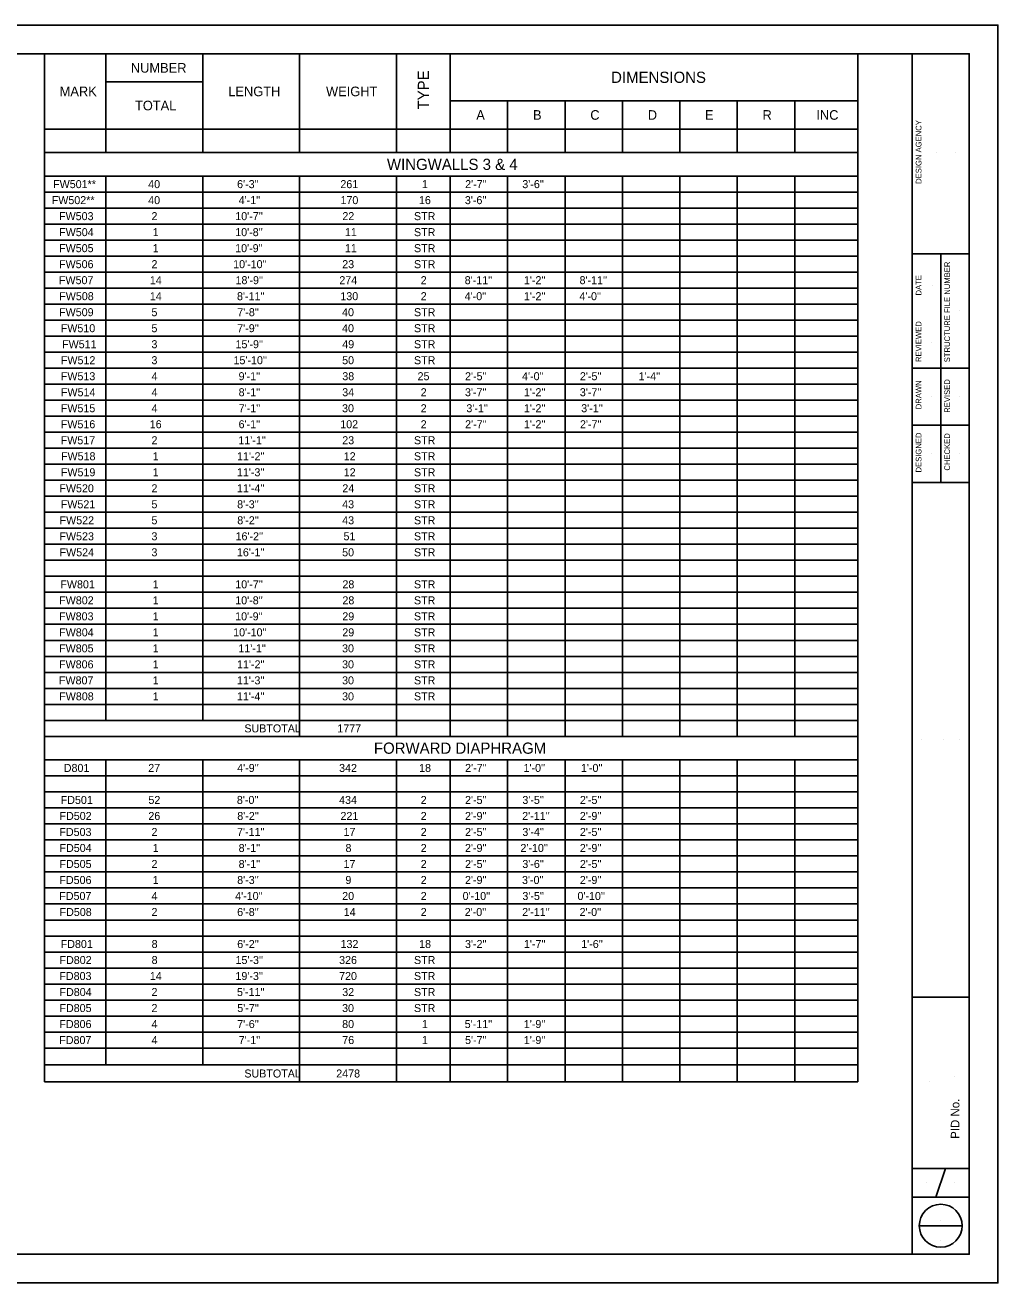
# Model space of a CAD drawing. Extents: x 0 to 34, y 0 to 22.
# Drawn here: x 16.98 to 34, y 0 to 22 of the extents above; entities that cross this region are included whole.
import ezdxf

# ---------------------------------------------------------------- set-up
doc = ezdxf.new("R2010")
doc.units = 0
for name, color, linetype in [('SH_Border', 7, 'Continuous'), ('SH_Cut_Line', 7, 'Continuous'), ('SH_Data', 7, 'Continuous'), ('SH_Text', 7, 'Continuous')]:
    doc.layers.add(name, color=color, linetype=linetype)

msp = doc.modelspace()

# ---------------------------------------------------------------- linework, layer by layer
at = {"layer": 'SH_Border'}
for p, q in [((32.5, 0.5), (32.5, 21.5)), ((32.5, 18), (33.5, 18)), ((33, 14), (33, 18)), ((32.5, 16), (33.5, 16)), ((32.5, 15), (33.5, 15)), ((32.5, 14), (33.5, 14)), ((32.5, 5), (33.5, 5)), ((32.5, 2), (33.5, 2)), ((32.917, 1.5), (33.083, 2)), ((32.5, 1.5), (33.5, 1.5))]:
    msp.add_line(p, q, dxfattribs=at)
msp.add_lwpolyline([(2, 21.5), (33.5, 21.5), (33.5, 0.5), (2, 0.5)], close=True, dxfattribs=at)
at = {"layer": 'SH_Cut_Line'}
msp.add_lwpolyline([(0, 22), (34, 22), (34, 0), (0, 0)], close=True, dxfattribs=at)
at = {"layer": 'SH_Data'}
for p, q in [((17.318, 21.5), (31.548, 21.5)), ((17.318, 21.5), (17.318, 19.771)), ((18.388, 21.5), (18.388, 19.771)), ((20.085, 21.5), (20.085, 19.771)), ((21.781, 21.5), (21.781, 19.771)), ((23.478, 21.5), (23.478, 19.771)), ((24.416, 21.5), (24.416, 19.771)), ((31.548, 21.5), (31.548, 19.771)), ((18.388, 21.006), (20.085, 21.006)), ((24.416, 20.676), (31.548, 20.676)), ((25.421, 20.676), (25.421, 19.771)), ((26.426, 20.676), (26.426, 19.771)), ((27.431, 20.676), (27.431, 19.771)), ((28.435, 20.676), (28.435, 19.771)), ((29.44, 20.676), (29.44, 19.771)), ((30.445, 20.676), (30.445, 19.771)), ((17.318, 20.182), (31.548, 20.182)), ((17.318, 19.771), (31.548, 19.771)), ((17.318, 19.771), (31.548, 19.771)), ((17.318, 19.771), (17.318, 3.514)), ((31.548, 19.771), (31.548, 3.514)), ((32.921, 19.773), (32.921, 19.773)), ((33.254, 19.773), (33.254, 19.773)), ((17.318, 19.359), (31.548, 19.359)), ((18.388, 19.359), (18.388, 9.839)), ((20.085, 19.359), (20.085, 9.839)), ((21.781, 19.359), (21.781, 9.559)), ((23.478, 19.359), (23.478, 9.559)), ((24.416, 19.359), (24.416, 9.559)), ((25.421, 19.359), (25.421, 9.559)), ((26.426, 19.359), (26.426, 9.559)), ((27.431, 19.359), (27.431, 9.559)), ((28.435, 19.359), (28.435, 9.559)), ((29.44, 19.359), (29.44, 9.559)), ((30.445, 19.359), (30.445, 9.559)), ((17.318, 19.079), (31.548, 19.079)), ((17.318, 18.799), (31.548, 18.799)), ((17.318, 18.519), (31.548, 18.519)), ((17.318, 18.239), (31.548, 18.239)), ((17.318, 17.959), (31.548, 17.959)), ((17.318, 17.679), (31.548, 17.679)), ((17.318, 17.399), (31.548, 17.399)), ((32.86, 17.449), (32.86, 17.449)), ((17.318, 17.119), (31.548, 17.119)), ((33.333, 17.009), (33.333, 17.009)), ((17.318, 16.839), (31.548, 16.839)), ((17.318, 16.559), (31.548, 16.559)), ((32.833, 16.447), (32.833, 16.447)), ((17.318, 16.279), (31.548, 16.279)), ((17.318, 15.999), (31.548, 15.999)), ((17.318, 15.719), (31.548, 15.719)), ((17.318, 15.439), (31.548, 15.439)), ((32.833, 15.51), (32.833, 15.51)), ((33.333, 15.51), (33.333, 15.51)), ((17.318, 15.159), (31.548, 15.159)), ((17.318, 14.879), (31.548, 14.879)), ((17.318, 14.599), (31.548, 14.599)), ((17.318, 14.319), (31.548, 14.319)), ((32.833, 14.51), (32.833, 14.51)), ((33.333, 14.509), (33.333, 14.509)), ((17.318, 14.039), (31.548, 14.039)), ((17.318, 13.759), (31.548, 13.759)), ((17.318, 13.479), (31.548, 13.479)), ((17.318, 13.199), (31.548, 13.199)), ((17.318, 12.919), (31.548, 12.919)), ((17.318, 12.639), (31.548, 12.639)), ((17.318, 12.359), (31.548, 12.359)), ((17.318, 12.079), (31.548, 12.079)), ((17.318, 11.799), (31.548, 11.799)), ((17.318, 11.519), (31.548, 11.519)), ((17.318, 11.239), (31.548, 11.239)), ((17.318, 10.959), (31.548, 10.959)), ((17.318, 10.679), (31.548, 10.679)), ((17.318, 10.399), (31.548, 10.399)), ((17.318, 10.119), (31.548, 10.119)), ((17.318, 9.839), (21.781, 9.839)), ((21.781, 9.839), (31.548, 9.839)), ((17.318, 9.559), (31.548, 9.559)), ((32.667, 9.5), (32.667, 9.5)), ((33.042, 9.5), (33.042, 9.5)), ((33.333, 9.5), (33.333, 9.5)), ((17.318, 9.147), (31.548, 9.147)), ((18.388, 9.147), (18.388, 3.811)), ((20.085, 9.147), (20.085, 3.811)), ((21.781, 9.147), (21.781, 3.514)), ((23.478, 9.147), (23.478, 3.514)), ((24.416, 9.147), (24.416, 3.514)), ((25.421, 9.147), (25.421, 3.514)), ((26.426, 9.147), (26.426, 3.514)), ((27.431, 9.147), (27.431, 3.514)), ((28.435, 9.147), (28.435, 3.514)), ((29.44, 9.147), (29.44, 3.514)), ((30.445, 9.147), (30.445, 3.514)), ((17.318, 8.867), (31.548, 8.867)), ((17.318, 8.587), (31.548, 8.587)), ((17.318, 8.307), (31.548, 8.307)), ((17.318, 8.027), (31.548, 8.027)), ((17.318, 7.747), (31.548, 7.747)), ((17.318, 7.467), (31.548, 7.467)), ((17.318, 7.187), (31.548, 7.187)), ((17.318, 6.907), (31.548, 6.907)), ((17.318, 6.627), (31.548, 6.627)), ((17.318, 6.347), (31.548, 6.347)), ((17.318, 6.067), (31.548, 6.067)), ((17.318, 5.787), (31.548, 5.787)), ((17.318, 5.507), (31.548, 5.507)), ((17.318, 5.227), (31.548, 5.227)), ((17.318, 4.947), (31.548, 4.947)), ((17.318, 4.667), (31.548, 4.667)), ((17.318, 4.387), (31.548, 4.387)), ((17.318, 4.107), (31.548, 4.107)), ((17.318, 3.811), (21.781, 3.811)), ((21.781, 3.811), (31.548, 3.811)), ((32.8, 3.53), (32.8, 3.53)), ((33.25, 3.618), (33.25, 3.618)), ((17.318, 3.514), (31.548, 3.514)), ((32.75, 1.75), (32.75, 1.75)), ((33.25, 1.75), (33.25, 1.75)), ((32.625, 1), (33.375, 1)), ((33, 1.085), (33, 1.085)), ((33, 0.745), (33, 0.745))]:
    msp.add_line(p, q, dxfattribs=at)
msp.add_circle((33, 1), 0.375, dxfattribs=at)

# ---------------------------------------------------------------- texts
for s, height, p in [('DESIGN AGENCY', 0.1, (32.663, 19.224)), ('STRUCTURE FILE NUMBER', 0.1, (33.163, 16.103)), ('DATE', 0.1, (32.663, 17.271)), ('REVIEWED', 0.1, (32.663, 16.108)), ('DRAWN', 0.1, (32.663, 15.281)), ('REVISED', 0.1, (33.163, 15.22)), ('DESIGNED', 0.1, (32.663, 14.175)), ('CHECKED', 0.1, (33.163, 14.208)), ('PID No.', 0.15, (33.327, 2.519))]:
    msp.add_text(s, height=height, rotation=90, dxfattribs=at).set_placement(p)
at = {"layer": 'SH_Text'}
for s, height, p in [('NUMBER', 0.168, (18.828, 21.169)), ('DIMENSIONS', 0.196, (27.232, 20.99)), ('MARK', 0.168, (17.582, 20.757)), ('LENGTH', 0.168, (20.533, 20.757)), ('WEIGHT', 0.168, (22.243, 20.757)), ('TOTAL', 0.168, (18.9, 20.51)), ('A', 0.168, (24.872, 20.345)), ('B', 0.168, (25.865, 20.345)), ('C', 0.168, (26.868, 20.345)), ('D', 0.168, (27.874, 20.345)), ('E', 0.168, (28.876, 20.345)), ('R', 0.168, (29.882, 20.345)), ('INC', 0.168, (30.824, 20.345)), ('WINGWALLS 3 & 4', 0.196, (23.309, 19.467)), ('FW501**', 0.14, (17.467, 19.149)), ('40', 0.14, (19.131, 19.149)), ("6'-3''", 0.14, (20.687, 19.149)), ('261', 0.14, (22.494, 19.149)), ('1', 0.14, (23.921, 19.149)), ("2'-7''", 0.14, (24.677, 19.149)), ("3'-6''", 0.14, (25.678, 19.149)), ('FW502**', 0.14, (17.443, 18.869)), ('40', 0.14, (19.131, 18.869)), ("4'-1''", 0.14, (20.714, 18.869)), ('170', 0.14, (22.496, 18.869)), ('16', 0.14, (23.869, 18.869)), ("3'-6''", 0.14, (24.673, 18.869)), ('FW503', 0.14, (17.571, 18.589)), ('2', 0.14, (19.189, 18.589)), ("10'-7''", 0.14, (20.655, 18.589)), ('22', 0.14, (22.529, 18.589)), ('STR', 0.14, (23.782, 18.589)), ('FW504', 0.14, (17.573, 18.309)), ('1', 0.14, (19.21, 18.309)), ("10'-8''", 0.14, (20.654, 18.309)), ('11', 0.14, (22.573, 18.309)), ('STR', 0.14, (23.782, 18.309)), ('FW505', 0.14, (17.572, 18.029)), ('1', 0.14, (19.21, 18.029)), ("10'-9''", 0.14, (20.653, 18.029)), ('11', 0.14, (22.573, 18.029)), ('STR', 0.14, (23.782, 18.029)), ('FW506', 0.14, (17.571, 17.749)), ('2', 0.14, (19.189, 17.749)), ("10'-10''", 0.14, (20.618, 17.749)), ('23', 0.14, (22.527, 17.749)), ('STR', 0.14, (23.782, 17.749)), ('FW507', 0.14, (17.569, 17.469)), ('14', 0.14, (19.16, 17.469)), ("18'-9''", 0.14, (20.659, 17.469)), ('274', 0.14, (22.476, 17.469)), ('2', 0.14, (23.9, 17.469)), ("8'-11''", 0.14, (24.67, 17.469)), ("1'-2''", 0.14, (25.706, 17.469)), ("8'-11''", 0.14, (26.68, 17.469)), ('FW508', 0.14, (17.574, 17.189)), ('14', 0.14, (19.16, 17.189)), ("8'-11''", 0.14, (20.685, 17.189)), ('130', 0.14, (22.494, 17.189)), ('2', 0.14, (23.9, 17.189)), ("4'-0''", 0.14, (24.669, 17.189)), ("1'-2''", 0.14, (25.706, 17.189)), ("4'-0''", 0.14, (26.678, 17.189)), ('FW509', 0.14, (17.572, 16.909)), ('5', 0.14, (19.188, 16.909)), ("7'-8''", 0.14, (20.69, 16.909)), ('40', 0.14, (22.524, 16.909)), ('STR', 0.14, (23.782, 16.909)), ('FW510', 0.14, (17.601, 16.629)), ('5', 0.14, (19.188, 16.629)), ("7'-9''", 0.14, (20.689, 16.629)), ('40', 0.14, (22.524, 16.629)), ('STR', 0.14, (23.782, 16.629)), ('FW511', 0.14, (17.624, 16.349)), ('3', 0.14, (19.188, 16.349)), ("15'-9''", 0.14, (20.659, 16.349)), ('49', 0.14, (22.527, 16.349)), ('STR', 0.14, (23.782, 16.349)), ('FW512', 0.14, (17.603, 16.069)), ('3', 0.14, (19.188, 16.069)), ("15'-10''", 0.14, (20.624, 16.069)), ('50', 0.14, (22.525, 16.069)), ('STR', 0.14, (23.782, 16.069)), ('FW513', 0.14, (17.602, 15.789)), ('4', 0.14, (19.19, 15.789)), ("9'-1''", 0.14, (20.713, 15.789)), ('38', 0.14, (22.528, 15.789)), ('25', 0.14, (23.845, 15.789)), ("2'-5''", 0.14, (24.676, 15.789)), ("4'-0''", 0.14, (25.674, 15.789)), ("2'-5''", 0.14, (26.686, 15.789)), ("1'-4''", 0.14, (27.714, 15.789)), ('FW514', 0.14, (17.604, 15.509)), ('4', 0.14, (19.19, 15.509)), ("8'-1''", 0.14, (20.714, 15.509)), ('34', 0.14, (22.527, 15.509)), ('2', 0.14, (23.9, 15.509)), ("3'-7''", 0.14, (24.675, 15.509)), ("1'-2''", 0.14, (25.706, 15.509)), ("3'-7''", 0.14, (26.685, 15.509)), ('FW515', 0.14, (17.602, 15.229)), ('4', 0.14, (19.19, 15.229)), ("7'-1''", 0.14, (20.715, 15.229)), ('30', 0.14, (22.524, 15.229)), ('2', 0.14, (23.9, 15.229)), ("3'-1''", 0.14, (24.699, 15.229)), ("1'-2''", 0.14, (25.706, 15.229)), ("3'-1''", 0.14, (26.709, 15.229)), ('FW516', 0.14, (17.602, 14.949)), ('16', 0.14, (19.158, 14.949)), ("6'-1''", 0.14, (20.713, 14.949)), ('102', 0.14, (22.492, 14.949)), ('2', 0.14, (23.9, 14.949)), ("2'-7''", 0.14, (24.677, 14.949)), ("1'-2''", 0.14, (25.706, 14.949)), ("2'-7''", 0.14, (26.687, 14.949)), ('FW517', 0.14, (17.6, 14.669)), ('2', 0.14, (19.189, 14.669)), ("11'-1''", 0.14, (20.709, 14.669)), ('23', 0.14, (22.527, 14.669)), ('STR', 0.14, (23.782, 14.669)), ('FW518', 0.14, (17.605, 14.389)), ('1', 0.14, (19.21, 14.389)), ("11'-2''", 0.14, (20.686, 14.389)), ('12', 0.14, (22.553, 14.389)), ('STR', 0.14, (23.782, 14.389)), ('FW519', 0.14, (17.603, 14.109)), ('1', 0.14, (19.21, 14.109)), ("11'-3''", 0.14, (20.684, 14.109)), ('12', 0.14, (22.553, 14.109)), ('STR', 0.14, (23.782, 14.109)), ('FW520', 0.14, (17.577, 13.829)), ('2', 0.14, (19.189, 13.829)), ("11'-4''", 0.14, (20.684, 13.829)), ('24', 0.14, (22.529, 13.829)), ('STR', 0.14, (23.782, 13.829)), ('FW521', 0.14, (17.601, 13.549)), ('5', 0.14, (19.188, 13.549)), ("8'-3''", 0.14, (20.688, 13.549)), ('43', 0.14, (22.526, 13.549)), ('STR', 0.14, (23.782, 13.549)), ('FW522', 0.14, (17.58, 13.269)), ('5', 0.14, (19.188, 13.269)), ("8'-2''", 0.14, (20.69, 13.269)), ('43', 0.14, (22.526, 13.269)), ('STR', 0.14, (23.782, 13.269)), ('FW523', 0.14, (17.578, 12.989)), ('3', 0.14, (19.188, 12.989)), ("16'-2''", 0.14, (20.66, 12.989)), ('51', 0.14, (22.549, 12.989)), ('STR', 0.14, (23.782, 12.989)), ('FW524', 0.14, (17.58, 12.709)), ('3', 0.14, (19.188, 12.709)), ("16'-1''", 0.14, (20.684, 12.709)), ('50', 0.14, (22.525, 12.709)), ('STR', 0.14, (23.782, 12.709)), ('FW801', 0.14, (17.594, 12.149)), ('1', 0.14, (19.21, 12.149)), ("10'-7''", 0.14, (20.655, 12.149)), ('28', 0.14, (22.53, 12.149)), ('STR', 0.14, (23.782, 12.149)), ('FW802', 0.14, (17.573, 11.869)), ('1', 0.14, (19.21, 11.869)), ("10'-8''", 0.14, (20.654, 11.869)), ('28', 0.14, (22.53, 11.869)), ('STR', 0.14, (23.782, 11.869)), ('FW803', 0.14, (17.571, 11.589)), ('1', 0.14, (19.21, 11.589)), ("10'-9''", 0.14, (20.653, 11.589)), ('29', 0.14, (22.528, 11.589)), ('STR', 0.14, (23.782, 11.589)), ('FW804', 0.14, (17.573, 11.309)), ('1', 0.14, (19.21, 11.309)), ("10'-10''", 0.14, (20.618, 11.309)), ('29', 0.14, (22.528, 11.309)), ('STR', 0.14, (23.782, 11.309)), ('FW805', 0.14, (17.572, 11.029)), ('1', 0.14, (19.21, 11.029)), ("11'-1''", 0.14, (20.709, 11.029)), ('30', 0.14, (22.524, 11.029)), ('STR', 0.14, (23.782, 11.029)), ('FW806', 0.14, (17.571, 10.749)), ('1', 0.14, (19.21, 10.749)), ("11'-2''", 0.14, (20.686, 10.749)), ('30', 0.14, (22.524, 10.749)), ('STR', 0.14, (23.782, 10.749)), ('FW807', 0.14, (17.569, 10.469)), ('1', 0.14, (19.21, 10.469)), ("11'-3''", 0.14, (20.684, 10.469)), ('30', 0.14, (22.524, 10.469)), ('STR', 0.14, (23.782, 10.469)), ('FW808', 0.14, (17.574, 10.189)), ('1', 0.14, (19.21, 10.189)), ("11'-4''", 0.14, (20.684, 10.189)), ('30', 0.14, (22.524, 10.189)), ('STR', 0.14, (23.782, 10.189)), ('SUBTOTAL', 0.14, (20.814, 9.629)), ('1777', 0.14, (22.441, 9.629)), ('FORWARD DIAPHRAGM', 0.196, (23.081, 9.255)), ('D801', 0.14, (17.654, 8.937)), ('27', 0.14, (19.132, 8.937)), ("4'-9''", 0.14, (20.688, 8.937)), ('342', 0.14, (22.472, 8.937)), ('18', 0.14, (23.872, 8.937)), ("2'-7''", 0.14, (24.677, 8.937)), ("1'-0''", 0.14, (25.699, 8.937)), ("1'-0''", 0.14, (26.704, 8.937)), ('FD501', 0.14, (17.6, 8.377)), ('52', 0.14, (19.135, 8.377)), ("8'-0''", 0.14, (20.683, 8.377)), ('434', 0.14, (22.472, 8.377)), ('2', 0.14, (23.9, 8.377)), ("2'-5''", 0.14, (24.676, 8.377)), ("3'-5''", 0.14, (25.679, 8.377)), ("2'-5''", 0.14, (26.686, 8.377)), ('FD502', 0.14, (17.579, 8.097)), ('26', 0.14, (19.134, 8.097)), ("8'-2''", 0.14, (20.69, 8.097)), ('221', 0.14, (22.496, 8.097)), ('2', 0.14, (23.9, 8.097)), ("2'-9''", 0.14, (24.675, 8.097)), ("2'-11''", 0.14, (25.676, 8.097)), ("2'-9''", 0.14, (26.685, 8.097)), ('FD503', 0.14, (17.577, 7.817)), ('2', 0.14, (19.189, 7.817)), ("7'-11''", 0.14, (20.686, 7.817)), ('17', 0.14, (22.549, 7.817)), ('2', 0.14, (23.9, 7.817)), ("2'-5''", 0.14, (24.676, 7.817)), ("3'-4''", 0.14, (25.679, 7.817)), ("2'-5''", 0.14, (26.686, 7.817)), ('FD504', 0.14, (17.579, 7.537)), ('1', 0.14, (19.21, 7.537)), ("8'-1''", 0.14, (20.714, 7.537)), ('8', 0.14, (22.584, 7.537)), ('2', 0.14, (23.9, 7.537)), ("2'-9''", 0.14, (24.675, 7.537)), ("2'-10''", 0.14, (25.645, 7.537)), ("2'-9''", 0.14, (26.685, 7.537)), ('FD505', 0.14, (17.578, 7.257)), ('2', 0.14, (19.189, 7.257)), ("8'-1''", 0.14, (20.714, 7.257)), ('17', 0.14, (22.549, 7.257)), ('2', 0.14, (23.9, 7.257)), ("2'-5''", 0.14, (24.676, 7.257)), ("3'-6''", 0.14, (25.678, 7.257)), ("2'-5''", 0.14, (26.686, 7.257)), ('FD506', 0.14, (17.577, 6.977)), ('1', 0.14, (19.21, 6.977)), ("8'-3''", 0.14, (20.688, 6.977)), ('9', 0.14, (22.582, 6.977)), ('2', 0.14, (23.9, 6.977)), ("2'-9''", 0.14, (24.675, 6.977)), ("3'-0''", 0.14, (25.673, 6.977)), ("2'-9''", 0.14, (26.685, 6.977)), ('FD507', 0.14, (17.575, 6.697)), ('4', 0.14, (19.19, 6.697)), ("4'-10''", 0.14, (20.653, 6.697)), ('20', 0.14, (22.526, 6.697)), ('2', 0.14, (23.9, 6.697)), ("0'-10''", 0.14, (24.634, 6.697)), ("3'-5''", 0.14, (25.679, 6.697)), ("0'-10''", 0.14, (26.643, 6.697)), ('FD508', 0.14, (17.58, 6.417)), ('2', 0.14, (19.189, 6.417)), ("6'-8''", 0.14, (20.688, 6.417)), ('14', 0.14, (22.553, 6.417)), ('2', 0.14, (23.9, 6.417)), ("2'-0''", 0.14, (24.67, 6.417)), ("2'-11''", 0.14, (25.676, 6.417)), ("2'-0''", 0.14, (26.68, 6.417)), ('FD801', 0.14, (17.6, 5.857)), ('8', 0.14, (19.191, 5.857)), ("6'-2''", 0.14, (20.689, 5.857)), ('132', 0.14, (22.497, 5.857)), ('18', 0.14, (23.872, 5.857)), ("3'-2''", 0.14, (24.675, 5.857)), ("1'-7''", 0.14, (25.706, 5.857)), ("1'-6''", 0.14, (26.709, 5.857)), ('FD802', 0.14, (17.579, 5.577)), ('8', 0.14, (19.191, 5.577)), ("15'-3''", 0.14, (20.659, 5.577)), ('326', 0.14, (22.472, 5.577)), ('STR', 0.14, (23.782, 5.577)), ('FD803', 0.14, (17.577, 5.297)), ('14', 0.14, (19.16, 5.297)), ("19'-3''", 0.14, (20.658, 5.297)), ('720', 0.14, (22.472, 5.297)), ('STR', 0.14, (23.782, 5.297)), ('FD804', 0.14, (17.579, 5.017)), ('2', 0.14, (19.189, 5.017)), ("5'-11''", 0.14, (20.685, 5.017)), ('32', 0.14, (22.527, 5.017)), ('STR', 0.14, (23.782, 5.017)), ('FD805', 0.14, (17.578, 4.737)), ('2', 0.14, (19.189, 4.737)), ("5'-7''", 0.14, (20.69, 4.737)), ('30', 0.14, (22.524, 4.737)), ('STR', 0.14, (23.782, 4.737)), ('FD806', 0.14, (17.577, 4.457)), ('4', 0.14, (19.19, 4.457)), ("7'-6''", 0.14, (20.689, 4.457)), ('80', 0.14, (22.525, 4.457)), ('1', 0.14, (23.921, 4.457)), ("5'-11''", 0.14, (24.67, 4.457)), ("1'-9''", 0.14, (25.704, 4.457)), ('FD807', 0.14, (17.575, 4.177)), ('4', 0.14, (19.19, 4.177)), ("7'-1''", 0.14, (20.715, 4.177)), ('76', 0.14, (22.527, 4.177)), ('1', 0.14, (23.921, 4.177)), ("5'-7''", 0.14, (24.676, 4.177)), ("1'-9''", 0.14, (25.704, 4.177)), ('SUBTOTAL', 0.14, (20.814, 3.592)), ('2478', 0.14, (22.422, 3.592))]:
    msp.add_text(s, height=height, dxfattribs=at).set_placement(p)
msp.add_text('TYPE', height=0.196, rotation=90, dxfattribs=at).set_placement((24.045, 20.525))

doc.saveas('drawing.dxf')
